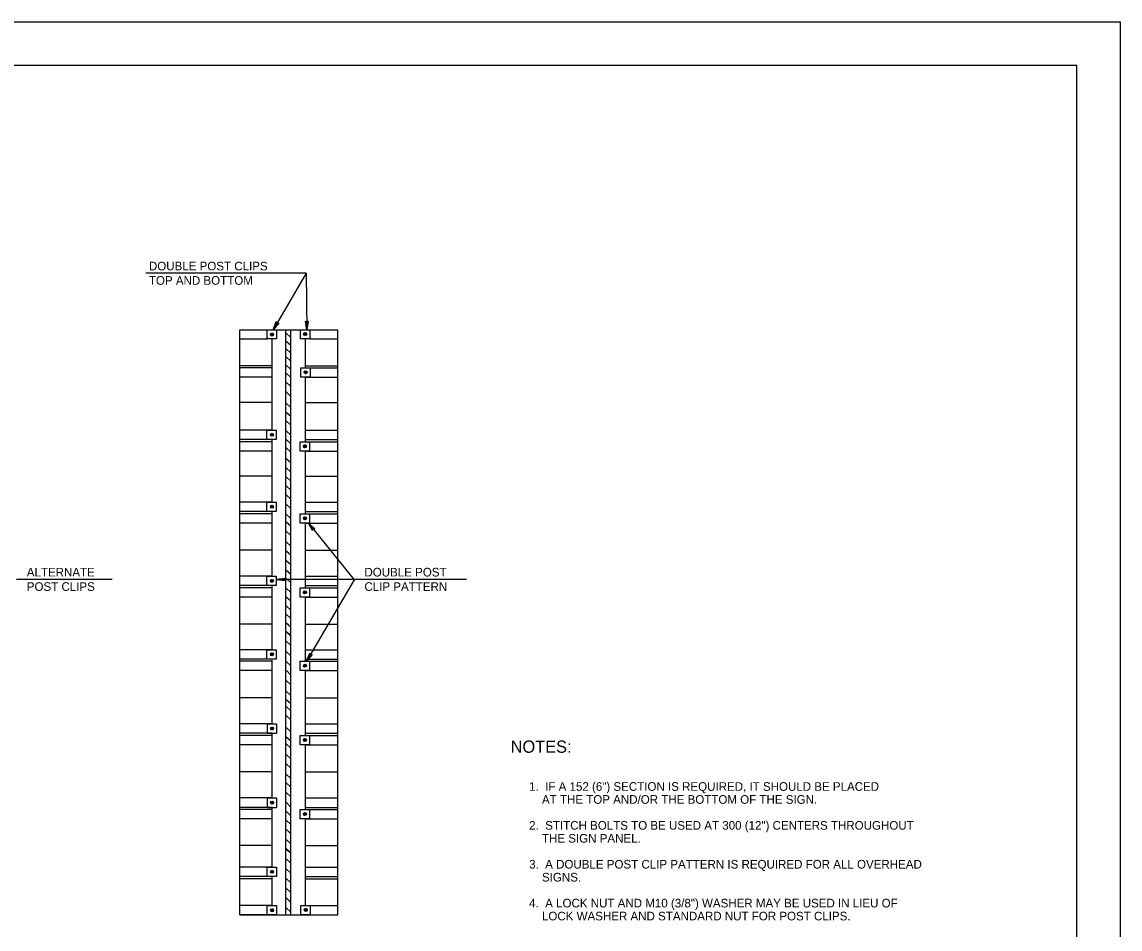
# Model space of a CAD drawing. Extents: x 647822 to 648727, y 298458 to 299646.
# Drawn here: x 648281.8 to 648663.3, y 299330.6 to 299645.6 of the extents above; entities that cross this region are included whole.
import ezdxf

# ---------------------------------------------------------------- set-up
doc = ezdxf.new("R2010")
doc.units = 0
for name, color, linetype in [('1', 7, 'Continuous'), ('2', 7, 'Continuous'), ('3', 7, 'Continuous'), ('XCS-GRID-MIN', 7, 'Continuous')]:
    doc.layers.add(name, color=color, linetype=linetype)

# ---------------------------------------------------------------- blocks, each defined once
blk = doc.blocks.new('RARROW')
at = {"layer": '3'}
blk.add_lwpolyline([(-2.2695, 0.285), (-2.184875, 0.12075), (0, 0), (-2.2695, 0.285), (-2.38575, 0.384625), (0, 0), (-2.183125, -0.108), (-2.262875, -0.2705), (0, 0), (-2.38575, -0.379125), (-2.262875, -0.2705)], dxfattribs=at)

msp = doc.modelspace()

# ---------------------------------------------------------------- linework, layer by layer
at = {"layer": '1'}
for p in [(647862.31, 299630.63), (648648.31, 299066.63)]:
    msp.add_line(p, (648648.31, 299630.63), dxfattribs=at)
at = {"layer": '2'}
for p, q in [((648380.55, 299558.35), (648324.89, 299558.35)), ((648380.55, 299558.35), (648369.05, 299538.73)), ((648380.55, 299558.35), (648380.8, 299538.73)), ((648357.55, 299335.47), (648357.55, 299538.73)), ((648357.55, 299538.73), (648391.55, 299538.73)), ((648367.05, 299535.6), (648367.05, 299538.73)), ((648370.3, 299538.73), (648370.3, 299535.6)), ((648373.55, 299335.47), (648373.55, 299538.73)), ((648375.18, 299535.98), (648373.55, 299537.6)), ((648375.18, 299335.47), (648375.18, 299538.73)), ((648378.55, 299538.73), (648381.8, 299538.73)), ((648378.55, 299535.6), (648378.55, 299538.73)), ((648381.8, 299538.73), (648381.8, 299535.6)), ((648391.55, 299335.47), (648391.55, 299538.73)), ((648357.55, 299535.6), (648367.05, 299535.6)), ((648370.3, 299535.6), (648367.05, 299535.6)), ((648368.8, 299503.85), (648368.8, 299535.6)), ((648375.18, 299533.23), (648373.55, 299534.73)), ((648381.8, 299535.6), (648378.55, 299535.6)), ((648380.3, 299525.48), (648380.3, 299535.6)), ((648381.8, 299535.6), (648391.55, 299535.6)), ((648375.18, 299530.6), (648373.55, 299532.23)), ((648368.8, 299526.23), (648357.55, 299526.23)), ((648375.18, 299527.85), (648373.55, 299529.48)), ((648375.18, 299524.98), (648373.55, 299526.6)), ((648380.3, 299526.23), (648391.55, 299526.23)), ((648368.8, 299525.48), (648357.55, 299525.48)), ((648368.8, 299522.23), (648357.55, 299522.23)), ((648375.18, 299522.1), (648373.55, 299523.73)), ((648378.68, 299525.48), (648381.93, 299525.48)), ((648378.68, 299522.23), (648378.68, 299525.48)), ((648381.93, 299522.23), (648378.68, 299522.23)), ((648380.3, 299525.48), (648391.55, 299525.48)), ((648380.3, 299525.48), (648380.3, 299525.48)), ((648380.3, 299522.23), (648391.55, 299522.23)), ((648380.3, 299499.85), (648380.3, 299522.23)), ((648381.93, 299525.48), (648381.93, 299522.23)), ((648375.18, 299518.98), (648373.55, 299520.6)), ((648375.18, 299515.6), (648373.55, 299517.23)), ((648368.8, 299513.48), (648357.55, 299513.48)), ((648375.18, 299511.73), (648373.55, 299513.35)), ((648380.3, 299513.48), (648391.55, 299513.48)), ((648375.18, 299508.6), (648373.55, 299510.1)), ((648375.18, 299505.6), (648373.55, 299507.23)), ((648368.8, 299503.85), (648357.55, 299503.85)), ((648366.93, 299503.85), (648370.18, 299503.85)), ((648366.93, 299500.6), (648366.93, 299503.85)), ((648370.18, 299503.85), (648370.18, 299500.6)), ((648375.18, 299502.1), (648373.55, 299503.73)), ((648380.3, 299503.85), (648391.55, 299503.85)), ((648368.8, 299500.6), (648357.55, 299500.6)), ((648368.8, 299499.85), (648357.55, 299499.85)), ((648370.18, 299500.6), (648366.93, 299500.6)), ((648368.8, 299478.85), (648368.8, 299500.6)), ((648375.18, 299499.1), (648373.55, 299500.73)), ((648378.43, 299499.85), (648381.68, 299499.85)), ((648378.43, 299496.6), (648378.43, 299499.85)), ((648380.3, 299500.6), (648391.55, 299500.6)), ((648380.3, 299499.85), (648391.55, 299499.85)), ((648381.68, 299499.85), (648381.68, 299496.6)), ((648368.8, 299496.6), (648357.55, 299496.6)), ((648375.18, 299496.23), (648373.55, 299497.85)), ((648381.68, 299496.6), (648378.43, 299496.6)), ((648380.3, 299496.6), (648391.55, 299496.6)), ((648380.3, 299474.85), (648380.3, 299496.6)), ((648375.18, 299492.48), (648373.55, 299493.98)), ((648368.8, 299487.85), (648357.55, 299487.85)), ((648375.18, 299489.23), (648373.55, 299490.85)), ((648380.3, 299487.85), (648391.55, 299487.85)), ((648375.18, 299486.1), (648373.55, 299487.73)), ((648375.18, 299482.98), (648373.55, 299484.6)), ((648375.18, 299479.85), (648373.55, 299481.48)), ((648368.8, 299478.85), (648357.55, 299478.85)), ((648366.93, 299478.85), (648370.18, 299478.85)), ((648366.93, 299475.6), (648366.93, 299478.85)), ((648370.18, 299478.85), (648370.18, 299475.6)), ((648375.18, 299476.6), (648373.55, 299478.23)), ((648380.3, 299478.85), (648391.55, 299478.85)), ((648368.8, 299475.6), (648357.55, 299475.6)), ((648368.8, 299474.85), (648357.55, 299474.85)), ((648370.18, 299475.6), (648366.93, 299475.6)), ((648368.8, 299453.47), (648368.8, 299475.6)), ((648375.18, 299473.23), (648373.55, 299474.85)), ((648378.43, 299474.85), (648381.68, 299474.85)), ((648378.43, 299471.6), (648378.43, 299474.85)), ((648380.3, 299475.6), (648391.55, 299475.6)), ((648380.3, 299474.85), (648391.55, 299474.85)), ((648381.68, 299474.85), (648381.68, 299471.6)), ((648368.8, 299471.6), (648357.55, 299471.6)), ((648375.18, 299470.48), (648373.55, 299471.98)), ((648375.18, 299467.23), (648373.55, 299468.85)), ((648381.68, 299471.6), (648378.43, 299471.6)), ((648380.3, 299471.6), (648391.55, 299471.6)), ((648380.3, 299449.36), (648380.3, 299471.6)), ((648381.32, 299471.6), (648397.18, 299451.85)), ((648375.18, 299463.6), (648373.55, 299465.23)), ((648368.8, 299462.23), (648357.55, 299462.23)), ((648375.18, 299460.48), (648373.55, 299461.98)), ((648380.3, 299462.23), (648391.55, 299462.23)), ((648375.18, 299457.1), (648373.55, 299458.6)), ((648375.18, 299453.73), (648373.55, 299455.23)), ((648313.17, 299451.98), (648279.88, 299451.98)), ((648368.8, 299453.1), (648357.55, 299453.1)), ((648368.8, 299449.85), (648357.55, 299449.85)), ((648366.93, 299453.1), (648370.18, 299453.1)), ((648366.93, 299449.85), (648366.93, 299453.1)), ((648370.18, 299449.85), (648366.93, 299449.85)), ((648368.55, 299453.1), (648368.55, 299453.1)), ((648368.8, 299427.6), (648368.8, 299449.85)), ((648370.18, 299453.1), (648370.18, 299449.85)), ((648397.43, 299451.98), (648370.3, 299451.98)), ((648375.18, 299450.85), (648373.55, 299452.48)), ((648380.3, 299453.1), (648391.55, 299453.1)), ((648380.3, 299449.85), (648391.55, 299449.85)), ((648397.18, 299451.85), (648380.71, 299423.6)), ((648436.31, 299451.98), (648397.18, 299451.98)), ((648368.8, 299449.1), (648357.55, 299449.1)), ((648368.8, 299445.85), (648357.55, 299445.85)), ((648375.18, 299447.48), (648373.55, 299449.1)), ((648375.18, 299444.48), (648373.55, 299445.98)), ((648378.43, 299449.1), (648381.68, 299449.1)), ((648378.43, 299445.85), (648378.43, 299449.1)), ((648381.68, 299445.85), (648378.43, 299445.85)), ((648380.05, 299449.1), (648380.05, 299449.1)), ((648380.3, 299449.1), (648391.55, 299449.1)), ((648380.3, 299445.85), (648391.55, 299445.85)), ((648380.3, 299423.6), (648380.3, 299445.85)), ((648381.68, 299449.1), (648381.68, 299445.85)), ((648375.18, 299441.35), (648373.55, 299442.98)), ((648375.18, 299438.48), (648373.55, 299440.1)), ((648368.8, 299436.48), (648357.55, 299436.48)), ((648375.18, 299435.48), (648373.55, 299436.98)), ((648380.3, 299436.48), (648391.55, 299436.48)), ((648375.05, 299432.48), (648373.55, 299433.98)), ((648375.18, 299432.48), (648373.55, 299433.98)), ((648375.18, 299429.1), (648373.55, 299430.73)), ((648368.68, 299427.6), (648357.43, 299427.6)), ((648366.93, 299427.6), (648370.18, 299427.6)), ((648366.93, 299424.35), (648366.93, 299427.6)), ((648368.55, 299427.6), (648368.55, 299427.6)), ((648370.18, 299427.6), (648370.18, 299424.35)), ((648375.18, 299425.48), (648373.55, 299427.1)), ((648380.3, 299427.6), (648391.55, 299427.6)), ((648368.68, 299424.35), (648357.43, 299424.35)), ((648368.68, 299423.6), (648357.43, 299423.6)), ((648370.18, 299424.35), (648366.93, 299424.35)), ((648368.8, 299401.85), (648368.8, 299424.02)), ((648375.18, 299421.98), (648373.55, 299423.6)), ((648378.43, 299423.6), (648381.68, 299423.6)), ((648378.43, 299420.35), (648378.43, 299423.6)), ((648380.05, 299423.6), (648380.05, 299423.6)), ((648380.3, 299424.35), (648391.55, 299424.35)), ((648380.3, 299423.6), (648391.55, 299423.6)), ((648381.68, 299423.6), (648381.68, 299420.35)), ((648368.68, 299420.35), (648357.43, 299420.35)), ((648375.18, 299418.73), (648373.68, 299420.35)), ((648381.68, 299420.35), (648378.43, 299420.35)), ((648380.3, 299420.35), (648391.55, 299420.35)), ((648380.3, 299397.85), (648380.3, 299420.27)), ((648375.18, 299415.35), (648373.55, 299416.98)), ((648375.18, 299411.73), (648373.55, 299413.35)), ((648368.8, 299410.85), (648357.55, 299410.85)), ((648375.18, 299408.85), (648373.55, 299410.35)), ((648375.18, 299406.35), (648373.55, 299407.98)), ((648380.3, 299410.85), (648391.55, 299410.85)), ((648375.18, 299403.23), (648373.55, 299404.85)), ((648368.8, 299401.85), (648357.55, 299401.85)), ((648367.18, 299401.85), (648370.3, 299401.85)), ((648367.18, 299398.6), (648367.18, 299401.85)), ((648368.8, 299401.85), (648368.8, 299401.85)), ((648370.3, 299401.85), (648370.3, 299398.6)), ((648375.18, 299399.1), (648373.55, 299400.73)), ((648380.3, 299401.85), (648391.55, 299401.85)), ((648368.8, 299398.6), (648357.55, 299398.6)), ((648368.8, 299397.85), (648357.55, 299397.85)), ((648368.8, 299398.6), (648367.18, 299398.6)), ((648367.18, 299398.6), (648370.3, 299398.6)), ((648368.8, 299376.1), (648368.8, 299398.6)), ((648375.18, 299395.85), (648373.55, 299397.35)), ((648378.43, 299397.85), (648381.68, 299397.85)), ((648378.43, 299394.6), (648378.43, 299397.85)), ((648380.05, 299397.85), (648380.05, 299397.85)), ((648380.3, 299398.6), (648391.55, 299398.6)), ((648380.3, 299397.85), (648391.55, 299397.85)), ((648381.68, 299397.85), (648381.68, 299394.6)), ((648368.8, 299394.6), (648357.55, 299394.6)), ((648375.18, 299393.35), (648373.55, 299394.98)), ((648381.68, 299394.6), (648378.43, 299394.6)), ((648380.3, 299394.6), (648391.55, 299394.6)), ((648380.3, 299372.1), (648380.3, 299394.6)), ((648375.18, 299389.73), (648373.55, 299391.35)), ((648368.8, 299385.23), (648357.55, 299385.23)), ((648375.18, 299386.48), (648373.55, 299388.1)), ((648380.3, 299385.23), (648391.55, 299385.23)), ((648375.18, 299382.85), (648373.55, 299384.48)), ((648375.18, 299379.85), (648373.55, 299381.48)), ((648375.18, 299376.48), (648373.55, 299378.1)), ((648368.8, 299376.1), (648357.55, 299376.1)), ((648367.18, 299376.1), (648370.3, 299376.1)), ((648367.18, 299372.85), (648367.18, 299376.1)), ((648368.8, 299376.1), (648368.8, 299376.1)), ((648370.3, 299376.1), (648370.3, 299372.85)), ((648375.05, 299373.1), (648373.55, 299374.73)), ((648380.3, 299376.1), (648391.55, 299376.1)), ((648368.8, 299372.85), (648357.55, 299372.85)), ((648368.8, 299372.1), (648357.55, 299372.1)), ((648368.8, 299372.85), (648367.18, 299372.85)), ((648367.18, 299372.85), (648370.3, 299372.85)), ((648368.8, 299352.1), (648368.8, 299372.85)), ((648375.05, 299370.1), (648373.55, 299371.6)), ((648378.43, 299372.1), (648381.68, 299372.1)), ((648378.43, 299368.85), (648378.43, 299372.1)), ((648380.3, 299372.85), (648391.55, 299372.85)), ((648380.3, 299372.1), (648391.55, 299372.1)), ((648381.68, 299372.1), (648381.68, 299368.85)), ((648368.8, 299368.85), (648357.55, 299368.85)), ((648375.18, 299366.85), (648373.55, 299368.48)), ((648381.68, 299368.85), (648378.43, 299368.85)), ((648380.3, 299368.85), (648391.55, 299368.85)), ((648380.3, 299348.05), (648380.3, 299368.85)), ((648375.18, 299363.6), (648373.68, 299365.1)), ((648368.8, 299359.6), (648357.55, 299359.6)), ((648375.18, 299360.23), (648373.55, 299361.85)), ((648375.18, 299360.23), (648373.55, 299361.85)), ((648375.05, 299357.23), (648373.55, 299358.73)), ((648375.18, 299356.83), (648373.55, 299358.46)), ((648380.3, 299359.6), (648391.55, 299359.6)), ((648375.18, 299353.44), (648373.55, 299355.06)), ((648368.68, 299352.1), (648357.55, 299352.1)), ((648367.05, 299352.1), (648370.3, 299352.1)), ((648367.05, 299348.85), (648367.05, 299352.1)), ((648370.3, 299352.1), (648370.3, 299348.85)), ((648375.18, 299350.04), (648373.55, 299351.67)), ((648380.43, 299352.1), (648391.55, 299352.1)), ((648368.68, 299348.85), (648357.55, 299348.85)), ((648368.8, 299348.05), (648357.55, 299348.05)), ((648370.3, 299348.85), (648367.05, 299348.85)), ((648368.8, 299338.72), (648368.8, 299348.85)), ((648375.18, 299346.65), (648373.55, 299348.28)), ((648380.3, 299348.85), (648391.55, 299348.85)), ((648380.3, 299338.72), (648380.3, 299348.05)), ((648380.3, 299348.05), (648391.55, 299348.05)), ((648375.18, 299343.26), (648373.55, 299344.88)), ((648375.18, 299339.86), (648373.55, 299341.49)), ((648368.68, 299338.72), (648357.55, 299338.72)), ((648357.55, 299335.47), (648391.55, 299335.47)), ((648368.68, 299335.47), (648357.55, 299335.47)), ((648367.05, 299338.72), (648370.3, 299338.72)), ((648367.05, 299335.47), (648367.05, 299338.72)), ((648370.3, 299335.47), (648367.05, 299335.47)), ((648370.3, 299338.72), (648370.3, 299335.47)), ((648375.18, 299336.47), (648373.55, 299338.09)), ((648378.68, 299338.72), (648381.93, 299338.72)), ((648378.68, 299335.47), (648378.68, 299338.72)), ((648381.93, 299335.47), (648378.68, 299335.47)), ((648380.43, 299338.72), (648391.55, 299338.72)), ((648380.43, 299335.47), (648391.55, 299335.47)), ((648381.93, 299338.72), (648381.93, 299335.47))]:
    msp.add_line(p, q, dxfattribs=at)
for points in [[(648368.55, 299537.48), (648368.43, 299537.23), (648368.43, 299536.85), (648368.68, 299536.73), (648368.93, 299536.85), (648369.05, 299537.1), (648369.05, 299537.35), (648368.93, 299537.48), (648368.68, 299537.48), (648368.55, 299537.23), (648368.55, 299537.1), (648368.55, 299536.98), (648368.68, 299536.98), (648368.8, 299537.1), (648368.93, 299537.23), (648368.8, 299537.35), (648368.8, 299537.23), (648368.68, 299537.1)], [(648380.05, 299537.6), (648379.93, 299537.23), (648379.93, 299536.98), (648380.18, 299536.85), (648380.43, 299536.98), (648380.55, 299537.23), (648380.55, 299537.48), (648380.43, 299537.6), (648380.18, 299537.48), (648380.05, 299537.23), (648380.05, 299537.1), (648380.05, 299537.1), (648380.18, 299536.98), (648380.3, 299537.23), (648380.43, 299537.23), (648380.3, 299537.48), (648380.3, 299537.35), (648380.18, 299537.1)], [(648380.18, 299524.35), (648380.05, 299523.98), (648380.05, 299523.73), (648380.3, 299523.48), (648380.55, 299523.6), (648380.68, 299523.85), (648380.68, 299524.1), (648380.55, 299524.35), (648380.43, 299524.23), (648380.18, 299523.98), (648380.18, 299523.85), (648380.18, 299523.73), (648380.3, 299523.73), (648380.43, 299523.85), (648380.55, 299523.98), (648380.55, 299524.1), (648380.43, 299523.98), (648380.3, 299523.85)], [(648368.55, 299502.6), (648368.3, 299502.35), (648368.3, 299501.98), (648368.55, 299501.85), (648368.8, 299501.98), (648368.93, 299502.23), (648368.93, 299502.48), (648368.8, 299502.6), (648368.68, 299502.6), (648368.43, 299502.35), (648368.43, 299502.23), (648368.43, 299502.1), (648368.68, 299502.1), (648368.8, 299502.23), (648368.8, 299502.35), (648368.8, 299502.48), (648368.68, 299502.35), (648368.55, 299502.23)], [(648380.05, 299498.6), (648379.8, 299498.35), (648379.8, 299497.98), (648380.05, 299497.85), (648380.3, 299497.98), (648380.43, 299498.23), (648380.43, 299498.48), (648380.3, 299498.6), (648380.18, 299498.6), (648379.93, 299498.35), (648379.93, 299498.23), (648379.93, 299498.1), (648380.18, 299498.1), (648380.3, 299498.23), (648380.3, 299498.35), (648380.3, 299498.48), (648380.18, 299498.35), (648380.05, 299498.23)], [(648368.55, 299477.6), (648368.3, 299477.35), (648368.3, 299476.98), (648368.55, 299476.85), (648368.8, 299476.98), (648368.93, 299477.23), (648368.93, 299477.48), (648368.8, 299477.6), (648368.68, 299477.6), (648368.43, 299477.35), (648368.43, 299477.23), (648368.43, 299477.1), (648368.68, 299477.1), (648368.8, 299477.23), (648368.8, 299477.35), (648368.8, 299477.48), (648368.68, 299477.35), (648368.55, 299477.23)], [(648380.05, 299473.6), (648379.8, 299473.35), (648379.8, 299472.98), (648380.05, 299472.85), (648380.3, 299472.98), (648380.43, 299473.23), (648380.43, 299473.48), (648380.3, 299473.6), (648380.18, 299473.6), (648379.93, 299473.35), (648379.93, 299473.23), (648379.93, 299473.1), (648380.18, 299473.1), (648380.3, 299473.23), (648380.3, 299473.35), (648380.3, 299473.48), (648380.18, 299473.35), (648380.05, 299473.23)], [(648368.55, 299451.85), (648368.3, 299451.6), (648368.3, 299451.23), (648368.55, 299451.1), (648368.8, 299451.23), (648368.93, 299451.48), (648368.93, 299451.73), (648368.8, 299451.85), (648368.68, 299451.85), (648368.43, 299451.6), (648368.43, 299451.48), (648368.43, 299451.35), (648368.68, 299451.35), (648368.8, 299451.48), (648368.8, 299451.6), (648368.8, 299451.73), (648368.68, 299451.6), (648368.55, 299451.48)], [(648380.05, 299447.85), (648379.8, 299447.6), (648379.8, 299447.23), (648380.05, 299447.1), (648380.3, 299447.23), (648380.43, 299447.48), (648380.43, 299447.73), (648380.3, 299447.85), (648380.18, 299447.85), (648379.93, 299447.6), (648379.93, 299447.48), (648379.93, 299447.35), (648380.18, 299447.35), (648380.3, 299447.48), (648380.3, 299447.6), (648380.3, 299447.73), (648380.18, 299447.6), (648380.05, 299447.48)], [(648368.55, 299426.35), (648368.3, 299426.1), (648368.3, 299425.73), (648368.55, 299425.6), (648368.8, 299425.73), (648368.93, 299425.98), (648368.93, 299426.23), (648368.8, 299426.35), (648368.68, 299426.35), (648368.43, 299426.1), (648368.43, 299425.98), (648368.43, 299425.85), (648368.68, 299425.85), (648368.8, 299425.98), (648368.8, 299426.1), (648368.8, 299426.23), (648368.68, 299426.1), (648368.55, 299425.98)], [(648380.05, 299422.35), (648379.8, 299422.1), (648379.8, 299421.73), (648380.05, 299421.6), (648380.3, 299421.73), (648380.43, 299421.98), (648380.43, 299422.23), (648380.3, 299422.35), (648380.18, 299422.35), (648379.93, 299422.1), (648379.93, 299421.98), (648379.93, 299421.85), (648380.18, 299421.85), (648380.3, 299421.98), (648380.3, 299422.1), (648380.3, 299422.23), (648380.18, 299422.1), (648380.05, 299421.98)], [(648368.55, 299400.6), (648368.43, 299400.23), (648368.43, 299399.98), (648368.68, 299399.85), (648368.93, 299399.98), (648369.05, 299400.23), (648369.05, 299400.48), (648368.93, 299400.6), (648368.8, 299400.48), (648368.55, 299400.23), (648368.55, 299400.1), (648368.55, 299400.1), (648368.68, 299399.98), (648368.8, 299400.23), (648368.93, 299400.23), (648368.93, 299400.48), (648368.8, 299400.35), (648368.68, 299400.1)], [(648380.05, 299396.6), (648379.8, 299396.35), (648379.8, 299395.98), (648380.05, 299395.85), (648380.3, 299395.98), (648380.43, 299396.23), (648380.43, 299396.48), (648380.3, 299396.6), (648380.18, 299396.6), (648379.93, 299396.35), (648379.93, 299396.23), (648379.93, 299396.1), (648380.18, 299396.1), (648380.3, 299396.23), (648380.3, 299396.35), (648380.3, 299396.48), (648380.18, 299396.35), (648380.05, 299396.23)], [(648368.55, 299374.85), (648368.43, 299374.48), (648368.43, 299374.23), (648368.68, 299374.1), (648368.93, 299374.23), (648369.05, 299374.48), (648369.05, 299374.73), (648368.93, 299374.85), (648368.8, 299374.73), (648368.55, 299374.48), (648368.55, 299374.35), (648368.55, 299374.35), (648368.68, 299374.23), (648368.8, 299374.48), (648368.93, 299374.48), (648368.93, 299374.73), (648368.8, 299374.6), (648368.68, 299374.35)], [(648380.05, 299370.85), (648379.8, 299370.6), (648379.8, 299370.23), (648380.05, 299370.1), (648380.3, 299370.23), (648380.43, 299370.48), (648380.43, 299370.73), (648380.3, 299370.85), (648380.18, 299370.85), (648379.93, 299370.6), (648379.93, 299370.48), (648379.93, 299370.35), (648380.18, 299370.35), (648380.3, 299370.48), (648380.3, 299370.6), (648380.3, 299370.73), (648380.18, 299370.6), (648380.05, 299370.48)], [(648368.55, 299350.85), (648368.43, 299350.48), (648368.43, 299350.23), (648368.68, 299350.1), (648368.93, 299350.23), (648369.05, 299350.35), (648369.05, 299350.73), (648368.93, 299350.85), (648368.68, 299350.85), (648368.55, 299350.48), (648368.55, 299350.35), (648368.55, 299350.23), (648368.68, 299350.23), (648368.8, 299350.35), (648368.93, 299350.48), (648368.93, 299350.73), (648368.8, 299350.6), (648368.68, 299350.35)], [(648368.55, 299337.47), (648368.43, 299337.09), (648368.43, 299336.84), (648368.68, 299336.72), (648368.93, 299336.84), (648369.05, 299336.97), (648369.05, 299337.34), (648368.93, 299337.47), (648368.68, 299337.47), (648368.55, 299337.09), (648368.55, 299336.97), (648368.55, 299336.84), (648368.68, 299336.84), (648368.8, 299336.97), (648368.93, 299337.09), (648368.93, 299337.34), (648368.8, 299337.22), (648368.68, 299336.97)], [(648380.3, 299337.59), (648380.05, 299337.22), (648380.05, 299336.97), (648380.43, 299336.84), (648380.68, 299336.97), (648380.8, 299337.22), (648380.8, 299337.47), (648380.55, 299337.59), (648380.43, 299337.59), (648380.3, 299337.22), (648380.18, 299337.22), (648380.3, 299336.97), (648380.43, 299336.97), (648380.55, 299337.22), (648380.68, 299337.22), (648380.55, 299337.47), (648380.43, 299337.34), (648380.43, 299337.22)]]:
    msp.add_lwpolyline(points, dxfattribs=at)
for centre in [(648368.68, 299537.06), (648380.21, 299537.23), (648380.36, 299523.97), (648368.64, 299502.26), (648380.14, 299498.26), (648368.64, 299477.26), (648380.14, 299473.26), (648368.64, 299451.51), (648380.14, 299447.51), (648368.64, 299426.01), (648380.14, 299422.01), (648368.74, 299400.23), (648380.14, 299396.26), (648368.74, 299374.48), (648380.14, 299370.51), (648368.73, 299350.48), (648368.73, 299337.1), (648380.43, 299337.22)]:
    msp.add_circle(centre, 0.525, dxfattribs=at)
at = {"layer": 'XCS-GRID-MIN'}
msp.add_lwpolyline([(647822.31, 299645.63), (648663.31, 299645.63), (648663.31, 299051.63), (647822.31, 299051.63)], close=True, dxfattribs=at)

# ---------------------------------------------------------------- block references
at = {"layer": '2'}
for p, xscale, yscale, rotation in [((648369.05, 299538.73), 1.2574347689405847, 1.3092961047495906, -120.49730409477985), ((648380.8, 299538.73), 1.2574347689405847, 1.3092961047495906, -90.00000000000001), ((648381.32, 299471.6), 1.2574347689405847, 1.3092961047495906, 128.86004763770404), ((648370.3, 299451.98), 1.2574347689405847, 1.3092961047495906, 180), ((648380.71, 299423.6), 1.2574347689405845, 1.3092961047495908, -120.047510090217)]:
    msp.add_blockref('RARROW', p, dxfattribs=dict(at, xscale=xscale, yscale=yscale, rotation=rotation))

# ---------------------------------------------------------------- texts
for s, height, p in [('DOUBLE POST CLIPS', 3, (648325.93, 299559.35)), ('TOP AND BOTTOM', 3, (648325.93, 299554.35)), ('ALTERNATE', 3, (648283.5, 299453.03)), ('DOUBLE POST', 3, (648400.8, 299453.03)), ('POST CLIPS', 3, (648283.5, 299448.03)), ('CLIP PATTERN', 3, (648400.8, 299448.03)), ('NOTES:', 4.25, (648451.6, 299391.81)), ('1.  IF A 152 (6") SECTION IS REQUIRED, IT SHOULD BE PLACED', 3, (648458.02, 299378.59)), ('    AT THE TOP AND/OR THE BOTTOM OF THE SIGN.', 3, (648458.02, 299374.09)), ('2.  STITCH BOLTS TO BE USED AT 300 (12") CENTERS THROUGHOUT', 3, (648458.02, 299365.09)), ('    THE SIGN PANEL.', 3, (648458.02, 299360.59)), ('3.  A DOUBLE POST CLIP PATTERN IS REQUIRED FOR ALL OVERHEAD', 3, (648458.02, 299351.59)), ('    SIGNS.', 3, (648458.02, 299347.09)), ('4.  A LOCK NUT AND M10 (3/8") WASHER MAY BE USED IN LIEU OF ', 3, (648458.02, 299338.09)), ('    LOCK WASHER AND STANDARD NUT FOR POST CLIPS.', 3, (648458.02, 299333.59))]:
    msp.add_text(s, height=height, dxfattribs=at).set_placement(p)

doc.saveas('drawing.dxf')
